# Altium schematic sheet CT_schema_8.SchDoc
size 297 x 239 mm
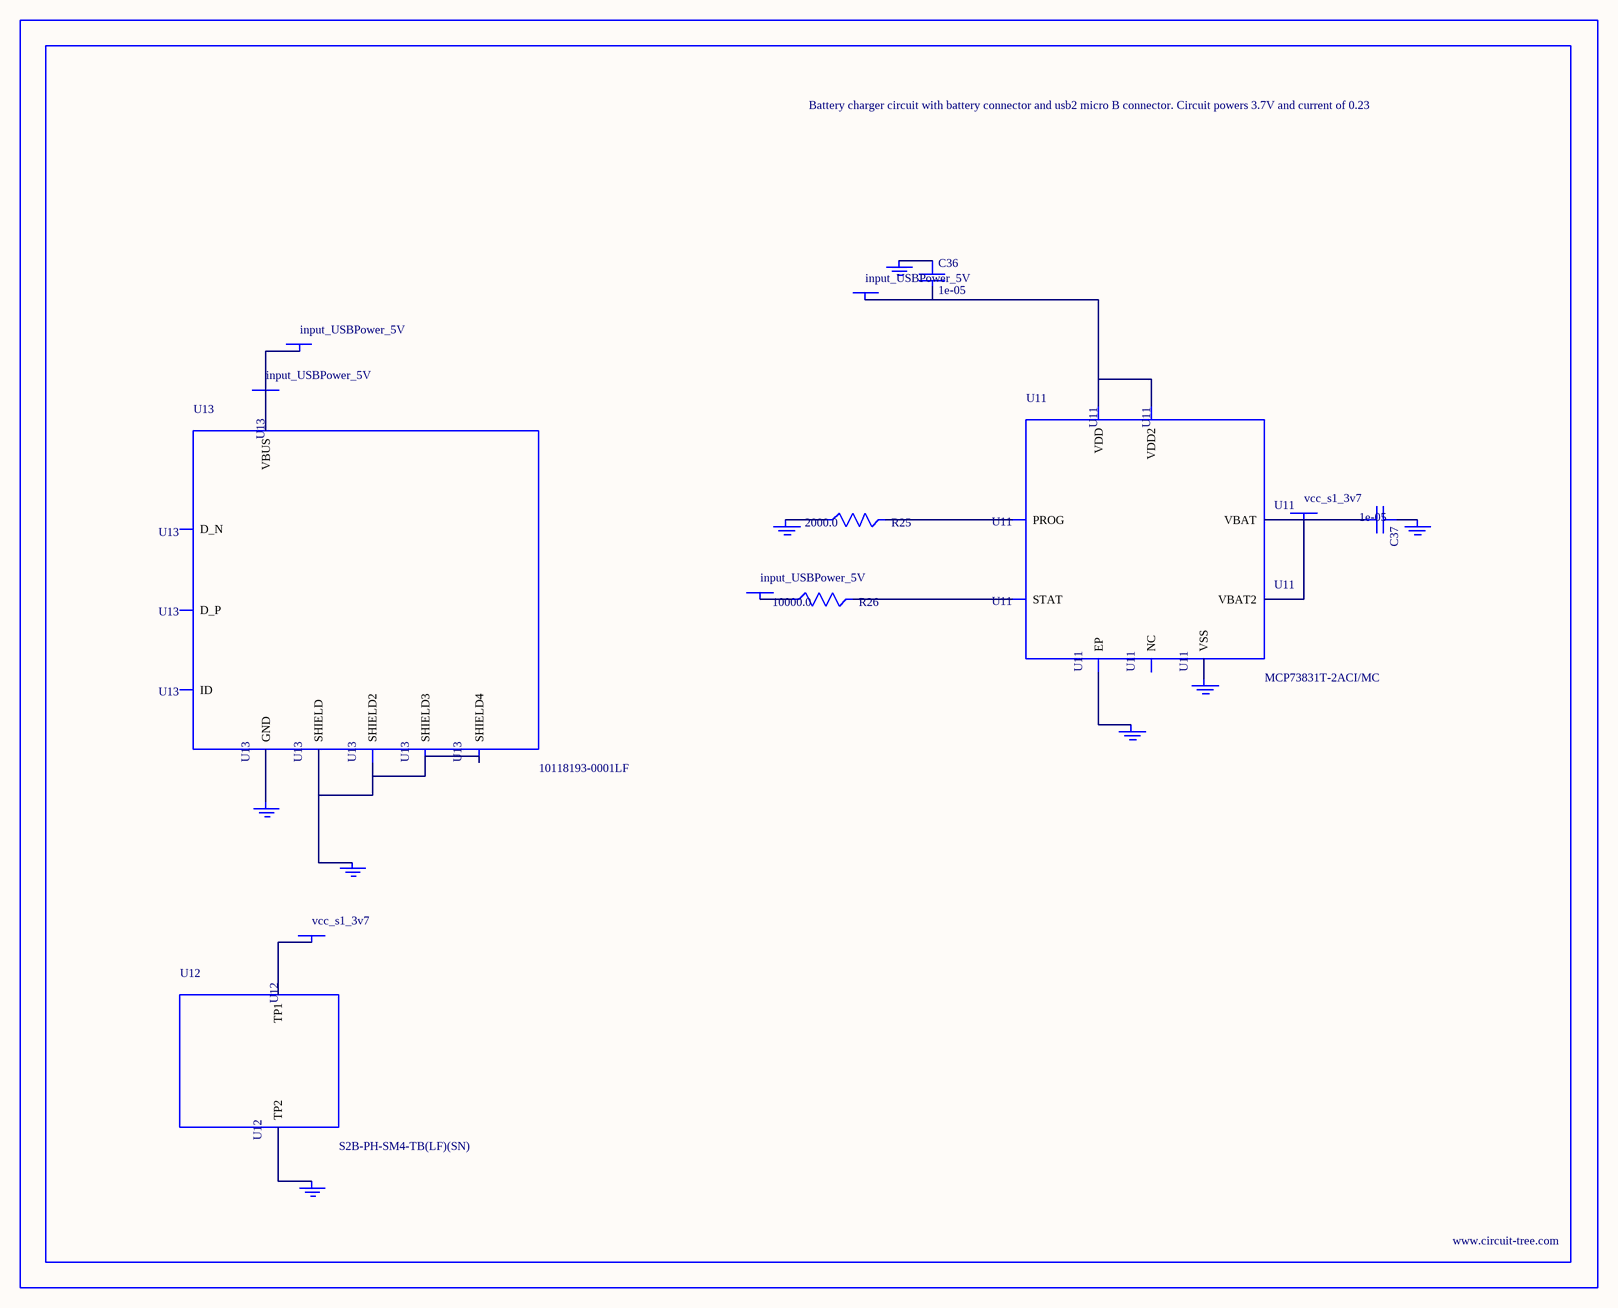
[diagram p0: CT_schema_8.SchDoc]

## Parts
BORDER7  (no value)
C36  1e-05  [C1206]
C37  1e-05  [C1206]
GND_INSTANCE_7_0  (no value)
GND_INSTANCE_7_1  (no value)
GND_INSTANCE_7_2  (no value)
GND_INSTANCE_7_3  (no value)
GND_INSTANCE_7_4  (no value)
GND_INSTANCE_7_5  (no value)
GND_INSTANCE_7_6  (no value)
GND_INSTANCE_7_7  (no value)
POWER_INSTANCE_7_0  input_USBPower_5V
POWER_INSTANCE_7_1  input_USBPower_5V
POWER_INSTANCE_7_2  vcc_s1_3v7
POWER_INSTANCE_7_3  vcc_s1_3v7
POWER_INSTANCE_7_4  input_USBPower_5V
POWER_INSTANCE_7_5  input_USBPower_5V
R25  2000.0  [R0603]
R26  10000.0  [R0603]
U11  MCP73831T-2ACI/MC  [DFN8_2X3MC]
U12  S2B-PH-SM4-TB(LF)(SN)  [JST-2-SMD]
U13  10118193-0001LF  [FCI_10118193-0001LF]

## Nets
NetC36_1: C36.1 GND_INSTANCE_7_0.0(GND)
NetC36_2: C36.2 POWER_INSTANCE_7_0.0(PWR) U11.1(VDD) U11.2(VDD2)
NetC37_1: C37.1 GND_INSTANCE_7_1.0(GND)
NetC37_2: C37.2 POWER_INSTANCE_7_2.0(PWR) U11.3(VBAT) U11.4(VBAT2)
NetGND_INSTANCE_7_2_0: GND_INSTANCE_7_2.0(GND) R25.1
NetGND_INSTANCE_7_3_0: GND_INSTANCE_7_3.0(GND) U11.9(EP)
NetGND_INSTANCE_7_4_0: GND_INSTANCE_7_4.0(GND) U11.6(VSS)
NetGND_INSTANCE_7_5_0: GND_INSTANCE_7_5.0(GND) U12.2(TP2)
NetGND_INSTANCE_7_6_0: GND_INSTANCE_7_6.0(GND) U13.6(SHIELD) U13.7(SHIELD2) U13.8(SHIELD3) U13.9(SHIELD4)
NetGND_INSTANCE_7_7_0: GND_INSTANCE_7_7.0(GND) U13.5(GND)
NetPOWER_INSTANCE_7_1_0: POWER_INSTANCE_7_1.0(PWR) R26.1
NetPOWER_INSTANCE_7_3_0: POWER_INSTANCE_7_3.0(PWR) U12.1(TP1)
NetPOWER_INSTANCE_7_4_0: POWER_INSTANCE_7_4.0(PWR) POWER_INSTANCE_7_5.0(PWR) U13.1(VBUS)
NetR25_2: R25.2 U11.8(PROG)
NetR26_2: R26.2 U11.5(STAT)

Not connected (* = marked no-connect by the designer): U11 7(NC); U13 2(D_N) 3(D_P) 4(ID)

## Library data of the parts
BORDER7 = BORDER_PAGE7
C36 C37 = C1206C106K3RACTU
GND_INSTANCE_7_0-GND_INSTANCE_7_7 = GND
POWER_INSTANCE_7_0-POWER_INSTANCE_7_5 = PWR
R25 = RC0603JR-072KL
R26 = RC0603JR-0710KL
